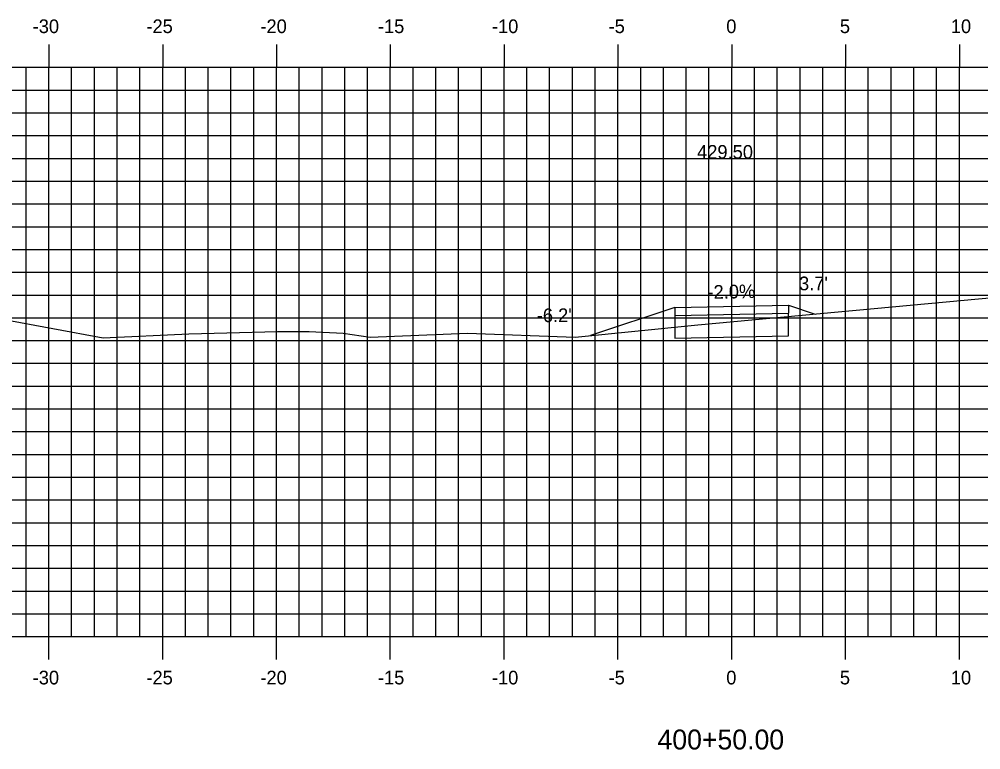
# Model space of a CAD drawing. Extents: x -161 to 764, y 111 to 210.
# Drawn here: x 122.87 to 165.11, y 122.2 to 154.28 of the extents above; entities that cross this region are included whole.
import ezdxf

# ---------------------------------------------------------------- set-up
doc = ezdxf.new("R2010")
doc.units = 0
for name, color, linetype in [('D_Property_Walkway_Paved', 7, 'Continuous'), ('D_Roadway_Centerline_Text', 7, 'Continuous'), ('D_Roadway_SubGrade', 7, 'Continuous'), ('D_Slope_Cut', 7, 'Continuous'), ('D_Text_Standard', 7, 'Continuous'), ('H_V ANNOTATION', 7, 'Continuous'), ('MAJOR', 7, 'Continuous'), ('MINOR', 7, 'Continuous'), ('S_Roadway_Centerline', 7, 'Continuous')]:
    doc.layers.add(name, color=color, linetype=linetype)

msp = doc.modelspace()

# ---------------------------------------------------------------- linework, layer by layer
at = {"layer": 'D_Property_Walkway_Paved'}
for p, q in [((151.666, 141.619), (156.665, 141.719)), ((151.666, 141.619), (151.666, 141.276)), ((156.665, 141.719), (156.665, 141.376)), ((151.666, 141.276), (156.665, 141.376))]:
    msp.add_line(p, q, dxfattribs=at)
at = {"layer": 'D_Roadway_SubGrade'}
msp.add_line((151.666, 141.276), (151.666, 140.276), dxfattribs=at)
msp.add_lwpolyline([(151.666, 140.276), (156.666, 140.376), (156.665, 141.376)], dxfattribs=at)
at = {"layer": 'D_Slope_Cut'}
for p, q in [((151.666, 141.619), (147.96, 140.384)), ((156.665, 141.719), (157.827, 141.332))]:
    msp.add_line(p, q, dxfattribs=at)
at = {"layer": 'MAJOR'}
for p, q in [((124.168, 153.171), (124.168, 152.169)), ((129.168, 153.171), (129.168, 152.169)), ((134.168, 153.171), (134.168, 152.169)), ((139.168, 153.171), (139.168, 152.169)), ((144.168, 153.171), (144.168, 152.169)), ((149.168, 153.171), (149.168, 152.169)), ((154.168, 153.171), (154.168, 152.169)), ((159.168, 153.171), (159.168, 152.169)), ((164.168, 153.171), (164.168, 152.169)), ((84.168, 152.169), (224.168, 152.169)), ((84.168, 152.169), (224.168, 152.169)), ((124.168, 127.169), (124.168, 152.169)), ((129.168, 127.169), (129.168, 152.169)), ((134.168, 127.169), (134.168, 152.169)), ((139.168, 127.169), (139.168, 152.169)), ((144.168, 127.169), (144.168, 152.169)), ((149.168, 127.169), (149.168, 152.169)), ((154.168, 127.169), (154.168, 152.169)), ((159.168, 127.169), (159.168, 152.169)), ((164.168, 127.169), (164.168, 152.169)), ((84.168, 147.169), (224.168, 147.169)), ((84.168, 142.169), (224.168, 142.169)), ((84.168, 137.169), (224.168, 137.169)), ((84.168, 132.169), (224.168, 132.169)), ((84.168, 127.169), (224.168, 127.169)), ((84.168, 127.169), (224.168, 127.169)), ((124.168, 126.167), (124.168, 127.169)), ((129.168, 126.167), (129.168, 127.169)), ((134.168, 126.167), (134.168, 127.169)), ((139.168, 126.167), (139.168, 127.169)), ((144.168, 126.167), (144.168, 127.169)), ((149.168, 126.167), (149.168, 127.169)), ((154.168, 126.167), (154.168, 127.169)), ((159.168, 126.167), (159.168, 127.169)), ((164.168, 126.167), (164.168, 127.169))]:
    msp.add_line(p, q, dxfattribs=at)
at = {"layer": 'MINOR'}
for p, q in [((123.168, 127.169), (123.168, 152.169)), ((125.168, 127.169), (125.168, 152.169)), ((126.168, 127.169), (126.168, 152.169)), ((127.168, 127.169), (127.168, 152.169)), ((128.168, 127.169), (128.168, 152.169)), ((130.168, 127.169), (130.168, 152.169)), ((131.168, 127.169), (131.168, 152.169)), ((132.168, 127.169), (132.168, 152.169)), ((133.168, 127.169), (133.168, 152.169)), ((135.168, 127.169), (135.168, 152.169)), ((136.168, 127.169), (136.168, 152.169)), ((137.168, 127.169), (137.168, 152.169)), ((138.168, 127.169), (138.168, 152.169)), ((140.168, 127.169), (140.168, 152.169)), ((141.168, 127.169), (141.168, 152.169)), ((142.168, 127.169), (142.168, 152.169)), ((143.168, 127.169), (143.168, 152.169)), ((145.168, 127.169), (145.168, 152.169)), ((146.168, 127.169), (146.168, 152.169)), ((147.168, 127.169), (147.168, 152.169)), ((148.168, 127.169), (148.168, 152.169)), ((150.168, 127.169), (150.168, 152.169)), ((151.168, 127.169), (151.168, 152.169)), ((152.168, 127.169), (152.168, 152.169)), ((153.168, 127.169), (153.168, 152.169)), ((155.168, 127.169), (155.168, 152.169)), ((156.168, 127.169), (156.168, 152.169)), ((157.168, 127.169), (157.168, 152.169)), ((158.168, 127.169), (158.168, 152.169)), ((160.168, 127.169), (160.168, 152.169)), ((161.168, 127.169), (161.168, 152.169)), ((162.168, 127.169), (162.168, 152.169)), ((163.168, 127.169), (163.168, 152.169)), ((84.168, 151.169), (224.168, 151.169)), ((84.168, 150.169), (224.168, 150.169)), ((84.168, 149.169), (224.168, 149.169)), ((84.168, 148.169), (224.168, 148.169)), ((84.168, 146.169), (224.168, 146.169)), ((84.168, 145.169), (224.168, 145.169)), ((84.168, 144.169), (224.168, 144.169)), ((84.168, 143.169), (224.168, 143.169)), ((84.168, 141.169), (224.168, 141.169)), ((84.168, 140.169), (224.168, 140.169)), ((84.168, 139.169), (224.168, 139.169)), ((84.168, 138.169), (224.168, 138.169)), ((84.168, 136.169), (224.168, 136.169)), ((84.168, 135.169), (224.168, 135.169)), ((84.168, 134.169), (224.168, 134.169)), ((84.168, 133.169), (224.168, 133.169)), ((84.168, 131.169), (224.168, 131.169)), ((84.168, 130.169), (224.168, 130.169)), ((84.168, 129.169), (224.168, 129.169)), ((84.168, 128.169), (224.168, 128.169))]:
    msp.add_line(p, q, dxfattribs=at)
at = {"layer": 'S_Roadway_Centerline'}
msp.add_lwpolyline([(84.168, 141.029), (87.203, 140.965), (88.029, 140.976), (88.313, 140.998), (88.651, 141.037), (90.373, 140.805), (93.242, 140.453), (95.167, 140.458), (101.949, 140.906), (102.274, 140.898), (102.611, 140.922), (111.988, 141.903), (114.233, 142.01), (122.137, 141.107), (126.555, 140.289), (130.319, 140.459), (134.216, 140.564), (135.604, 140.561), (137.09, 140.487), (138.288, 140.324), (142.564, 140.487), (147.286, 140.317), (152.685, 140.854), (168.169, 142.293)], dxfattribs=at)

# ---------------------------------------------------------------- texts
at = {"layer": 'D_Roadway_Centerline_Text'}
msp.add_text('429.50', height=0.6, dxfattribs=at).set_placement((152.646, 148.154))
at = {"layer": 'D_Text_Standard'}
for s, p in [("3.7'", (157.124, 142.378)), ("-6.2'", (145.603, 140.98))]:
    msp.add_text(s, height=0.6, dxfattribs=at).set_placement(p)
msp.add_text('-2.0%', height=0.6, rotation=1.1458, dxfattribs=at).set_placement((153.108, 141.997))
at = {"layer": 'H_V ANNOTATION'}
for s, height, p in [('-30', 0.6, (123.456, 153.669)), ('-25', 0.6, (128.453, 153.669)), ('-20', 0.6, (133.461, 153.669)), ('-15', 0.6, (138.624, 153.669)), ('-10', 0.6, (143.632, 153.669)), ('-5', 0.6, (148.758, 153.669)), ('0', 0.6, (153.927, 153.669)), ('5', 0.6, (158.919, 153.669)), ('10', 0.6, (163.793, 153.669)), ('-30', 0.6, (123.456, 125.069)), ('-25', 0.6, (128.453, 125.069)), ('-20', 0.6, (133.461, 125.069)), ('-15', 0.6, (138.624, 125.069)), ('-10', 0.6, (143.632, 125.069)), ('-5', 0.6, (148.758, 125.069)), ('0', 0.6, (153.927, 125.069)), ('5', 0.6, (158.919, 125.069)), ('10', 0.6, (163.793, 125.069)), ('400+50.00', 0.875, (150.906, 122.212))]:
    msp.add_text(s, height=height, rotation=360, dxfattribs=at).set_placement(p)

doc.saveas('drawing.dxf')
